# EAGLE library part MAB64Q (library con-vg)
CONNECTOR male, 64 pins, type Q, rows AB, grid 2.54 mm
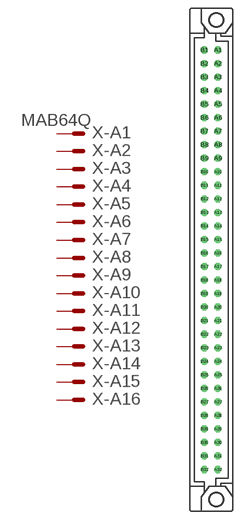
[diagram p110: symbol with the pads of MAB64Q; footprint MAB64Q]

Designator prefix X; gates -A1=MVAL -A2=MAL -A3=MAL -A4=MAL -A5=MAL -A6=MAL -A7=MAL -A8=MAL -A9=MAL -A10=MAL -A11=MAL -A12=MAL -A13=MAL -A14=MAL -A15=MAL -A16=MAL -A17=MAL -A18=MAL -A19=MAL -A20=MAL -A21=MAL -A22=MAL -A23=MAL -A24=MAL -A25=MAL -A26=MAL -A27=MAL -A28=MAL -A29=MAL -A30=MAL -A31=MAL -A32=MAL -B1=MVAL -B2=MAL -B3=MAL -B4=MAL -B5=MAL -B6=MAL -B7=MAL -B8=MAL -B9=MAL -B10=MAL -B11=MAL -B12=MAL -B13=MAL -B14=MAL -B15=MAL -B16=MAL -B17=MAL -B18=MAL -B19=MAL -B20=MAL -B21=MAL -B22=MAL -B23=MAL -B24=MAL -B25=MAL -B26=MAL -B27=MAL -B28=MAL -B29=MAL -B30=MAL -B31=MAL -B32=MAL

## MAB64Q  [MAB64Q]
A1  -A1:S  pas
A2  -A2:S  pas
A3  -A3:S  pas
A4  -A4:S  pas
A5  -A5:S  pas
A6  -A6:S  pas
A7  -A7:S  pas
A8  -A8:S  pas
A9  -A9:S  pas
A10  -A10:S  pas
A11  -A11:S  pas
A12  -A12:S  pas
A13  -A13:S  pas
A14  -A14:S  pas
A15  -A15:S  pas
A16  -A16:S  pas
A17  -A17:S  pas
A18  -A18:S  pas
A19  -A19:S  pas
A20  -A20:S  pas
A21  -A21:S  pas
A22  -A22:S  pas
A23  -A23:S  pas
A24  -A24:S  pas
A25  -A25:S  pas
A26  -A26:S  pas
A27  -A27:S  pas
A28  -A28:S  pas
A29  -A29:S  pas
A30  -A30:S  pas
A31  -A31:S  pas
A32  -A32:S  pas
B1  -B1:S  pas
B2  -B2:S  pas
B3  -B3:S  pas
B4  -B4:S  pas
B5  -B5:S  pas
B6  -B6:S  pas
B7  -B7:S  pas
B8  -B8:S  pas
B9  -B9:S  pas
B10  -B10:S  pas
B11  -B11:S  pas
B12  -B12:S  pas
B13  -B13:S  pas
B14  -B14:S  pas
B15  -B15:S  pas
B16  -B16:S  pas
B17  -B17:S  pas
B18  -B18:S  pas
B19  -B19:S  pas
B20  -B20:S  pas
B21  -B21:S  pas
B22  -B22:S  pas
B23  -B23:S  pas
B24  -B24:S  pas
B25  -B25:S  pas
B26  -B26:S  pas
B27  -B27:S  pas
B28  -B28:S  pas
B29  -B29:S  pas
B30  -B30:S  pas
B31  -B31:S  pas
B32  -B32:S  pas

## Footprint MAB64Q (pad centres in mm)
CONNECTOR male, 64 pins, type Q, rows AB, grid 2.54 mm
drill 0.813 octagon: A1 1.27,39.37; A2 1.27,36.83; A3 1.27,34.29; A4 1.27,31.75; A5 1.27,29.21; A6 1.27,26.67; A7 1.27,24.13; A8 1.27,21.59; A9 1.27,19.05; A10 1.27,16.51; A11 1.27,13.97; A12 1.27,11.43; A13 1.27,8.89; A14 1.27,6.35; A15 1.27,3.81; A16 1.27,1.27; A17 1.27,-1.27; A18 1.27,-3.81; A19 1.27,-6.35; A20 1.27,-8.89; A21 1.27,-11.43; A22 1.27,-13.97; A23 1.27,-16.51; A24 1.27,-19.05; A25 1.27,-21.59; A26 1.27,-24.13; A27 1.27,-26.67; A28 1.27,-29.21; A29 1.27,-31.75; A30 1.27,-34.29; A31 1.27,-36.83; A32 1.27,-39.37; B1 -1.27,39.37; B2 -1.27,36.83; B3 -1.27,34.29; B4 -1.27,31.75; B5 -1.27,29.21; B6 -1.27,26.67; B7 -1.27,24.13; B8 -1.27,21.59; B9 -1.27,19.05; B10 -1.27,16.51; B11 -1.27,13.97; B12 -1.27,11.43; B13 -1.27,8.89; B14 -1.27,6.35; B15 -1.27,3.81; B16 -1.27,1.27; B17 -1.27,-1.27; B18 -1.27,-3.81; B19 -1.27,-6.35; B20 -1.27,-8.89; B21 -1.27,-11.43; B22 -1.27,-13.97; B23 -1.27,-16.51; B24 -1.27,-19.05; B25 -1.27,-21.59; B26 -1.27,-24.13; B27 -1.27,-26.67; B28 -1.27,-29.21; B29 -1.27,-31.75; B30 -1.27,-34.29; B31 -1.27,-36.83; B32 -1.27,-39.37
hole 2.794 at 0.965,-45
hole 2.794 at 0.965,45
